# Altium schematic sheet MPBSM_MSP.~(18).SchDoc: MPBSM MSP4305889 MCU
size 431 x 279 mm; Date: Not shown in title block; ApprovedBy: Not shown in title block; CheckedBy: Not shown in title block; Author: Not shown in title block; CompanyName: Not shown in title block; Engineer: Not shown in title block; Organization: Not shown in title block; Address1: Not shown in title block; Address2: Not shown in title block; Address3: Not shown in title block; Address4: Not shown in title block; DocumentNumber: 6; Revision: Use project parameter SCH_Rev; SheetNumber: 6; SheetTotal: 12; PageSetup: Record=PageOptions¦CenterHorizontal=True¦CenterVertical=True¦PrintScale=0.62¦XCorrection=1.00¦YCorrection=1.00¦PrintKind=0¦BorderSize=5000000¦LeftOffset=0¦BottomOffset=0¦Orientation=2¦PaperLength=1000¦PaperWidth=1000¦Scale=100¦PaperSource=15¦PrintQuality=600¦MediaType=1¦DitherType=10¦PaperKind=Letter¦PrintScaleMode=1
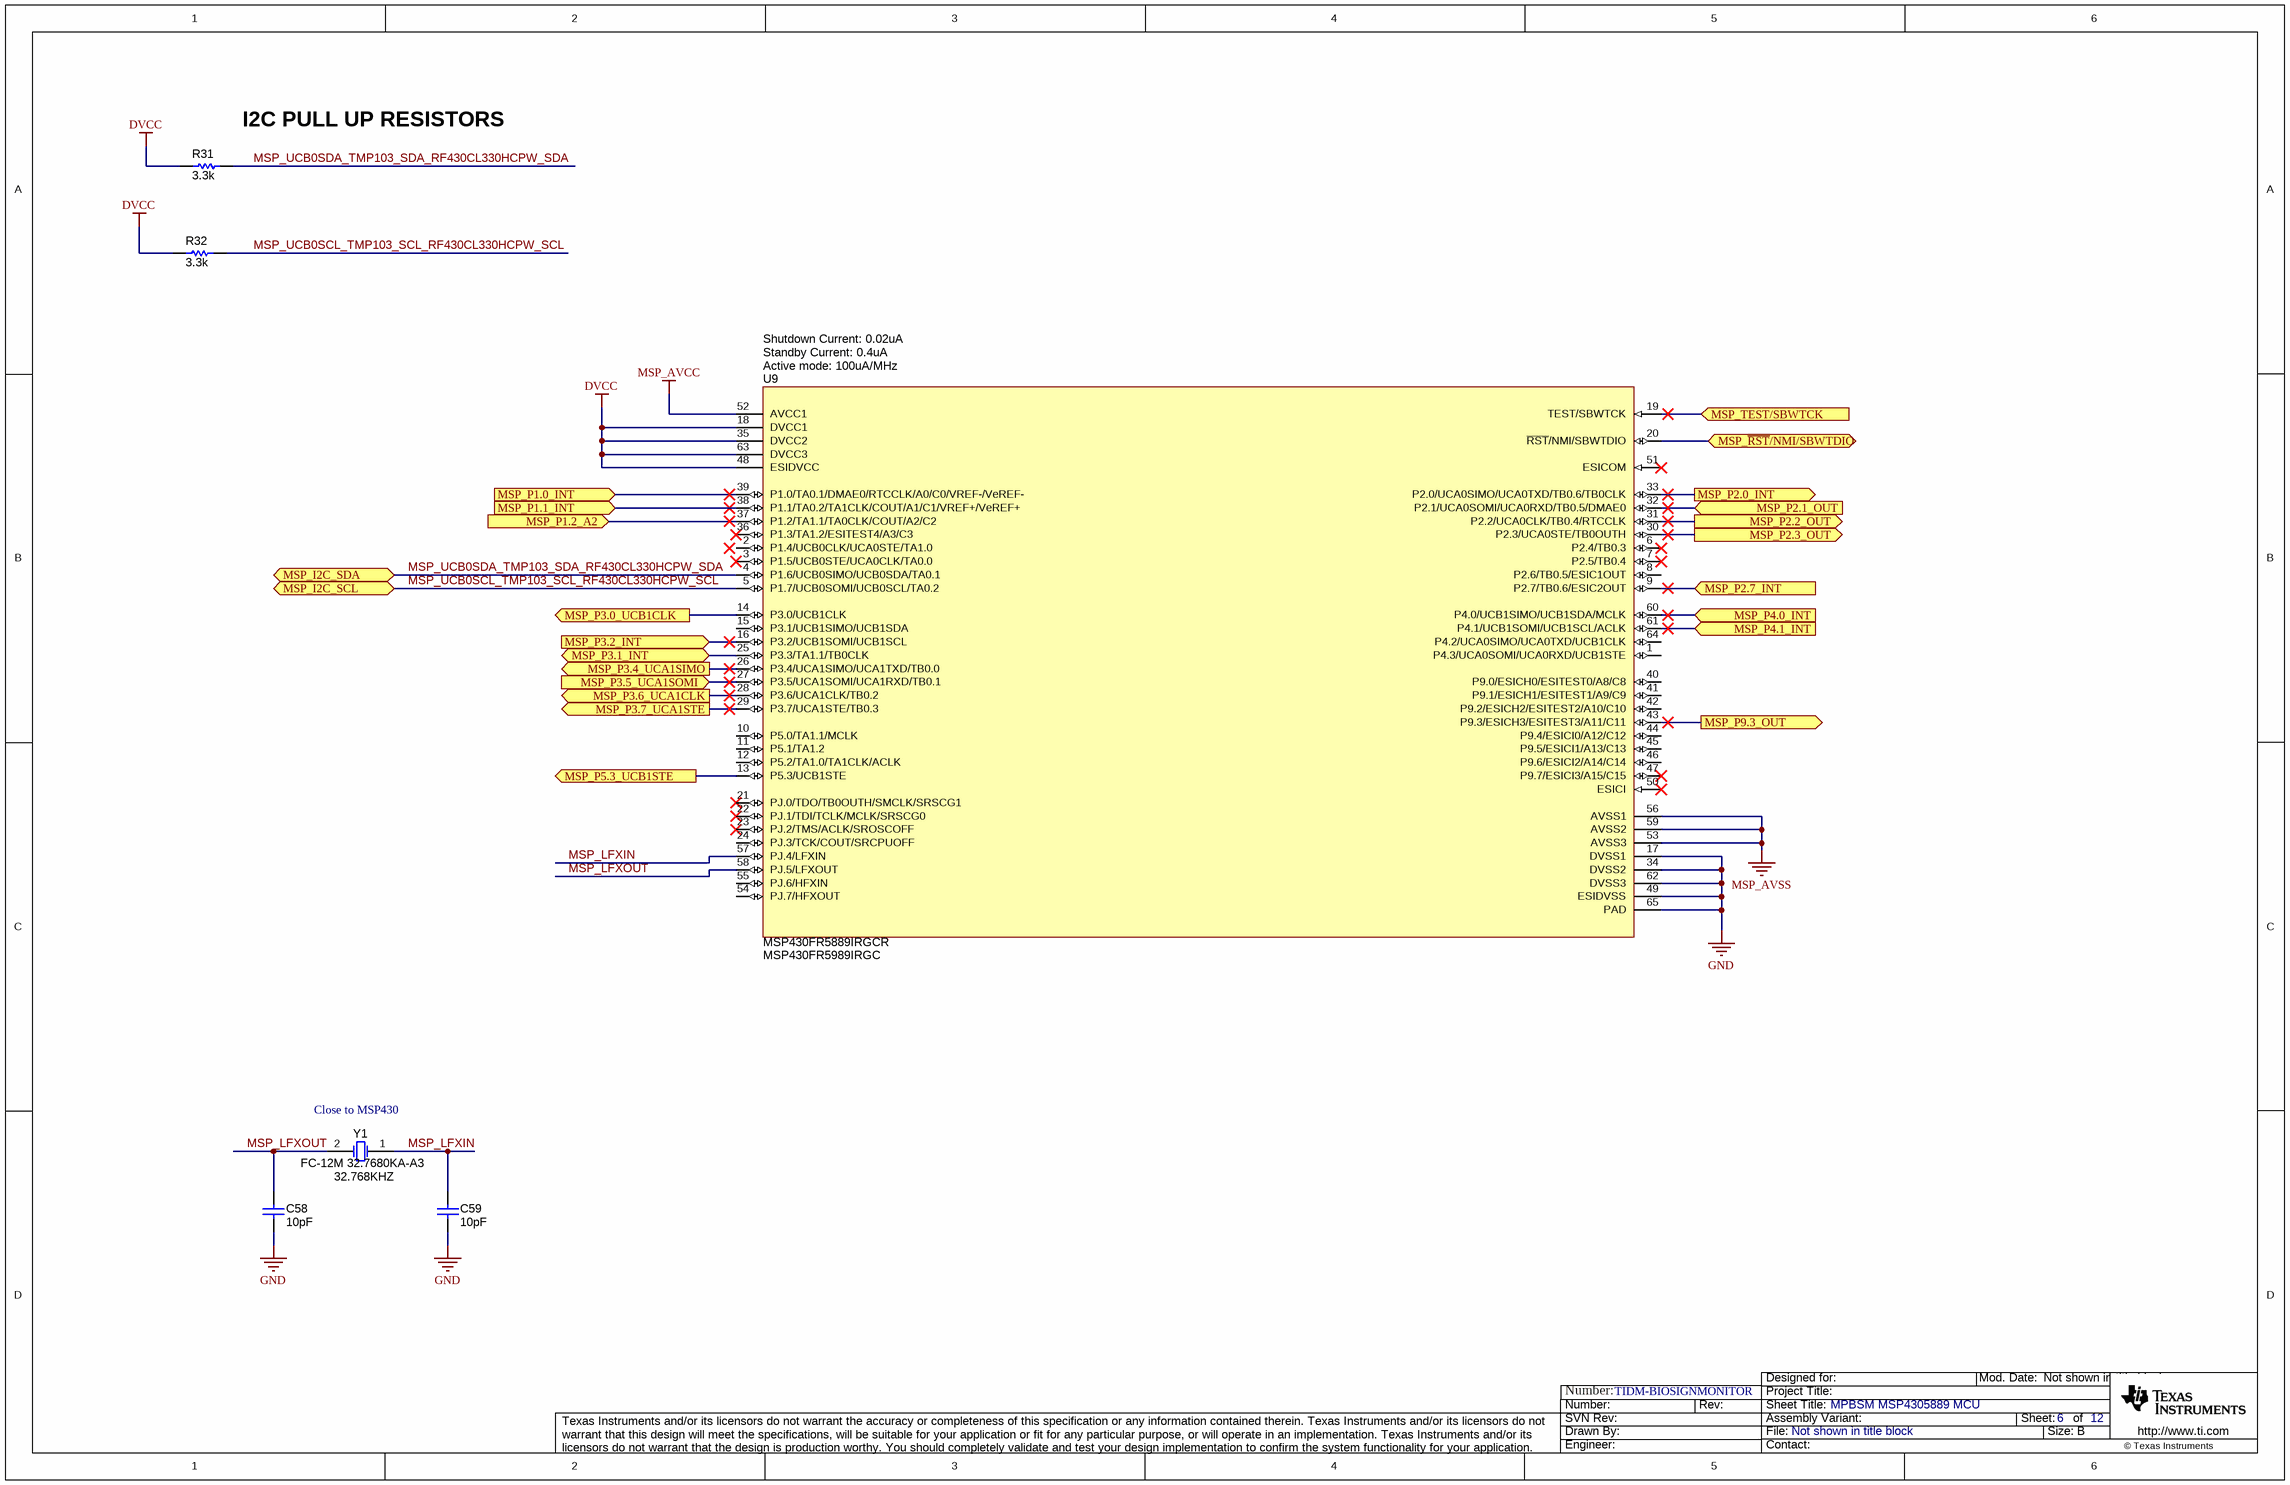
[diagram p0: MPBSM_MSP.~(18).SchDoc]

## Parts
C58  ValueDisplayed: 10pF  [0603]  (hidden comment: 06035A100JAT2A)
C59  ValueDisplayed: 10pF  [0603]  (hidden comment: 06035A100JAT2A)
R31  ValueDisplayed: 3.3k  [0402]  (hidden comment: CRCW04023K30JNED)
R32  ValueDisplayed: 3.3k  [0402]  (hidden comment: CRCW04023K30JNED)
U9  MSP430FR5889IRGCR  Alternate PartNumber: MSP430FR5989IRGC  Active mode: 100uA/MHz  Standby Current: 0.4uA  Shutdown Current: 0.02uA  [RGC0064B]
Y1  FC-12M 32.7680KA-A3  Frequency: 32.768KHZ  [Epson_FC-12M]

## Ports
MSP_I2C_SCL (bidir), MSP_I2C_SDA (bidir), MSP_P1.0_INT (in), MSP_P1.1_INT (in), MSP_P1.2_A2 (in), MSP_P2.0_INT (out), MSP_P2.1_OUT (in), MSP_P2.2_OUT (out), MSP_P2.3_OUT (out), MSP_P2.7_INT (in), MSP_P3.0_UCB1CLK (out), MSP_P3.1_INT (bidir), MSP_P3.2_INT (in), MSP_P3.4_UCA1SIMO (out), MSP_P3.5_UCA1SOMI (in), MSP_P3.6_UCA1CLK (out), MSP_P3.7_UCA1STE (out), MSP_P4.0_INT (in), MSP_P4.1_INT (in), MSP_P5.3_UCB1STE (out), MSP_P9.3_OUT (out), MSP_TEST/SBWTCK (in), MSP_~{RST}/NMI/SBWTDIO (bidir)

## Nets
DVCC: R31.1 R32.1 U9.18(DVCC1) U9.35(DVCC2) U9.48(ESIDVCC) U9.63(DVCC3)
GND: C58.2 C59.2 U9.17(DVSS1) U9.34(DVSS2) U9.49(ESIDVSS) U9.62(DVSS3) U9.65(PAD)
MSP_AVCC: U9.52(AVCC1)
MSP_AVSS: U9.53(AVSS3) U9.56(AVSS1) U9.59(AVSS2)
MSP_LFXIN: C59.1 U9.57(PJ.4/LFXIN) Y1.1(OSC1)
MSP_LFXOUT: C58.1 U9.58(PJ.5/LFXOUT) Y1.2(OSC2)
MSP_P1.0_INT: U9.39(P1.0/TA0.1/DMAE0/RTCCLK/A0/C0/VREF-/VeREF-) ; port MSP_P1.0_INT
MSP_P1.1_INT: U9.38(P1.1/TA0.2/TA1CLK/COUT/A1/C1/VREF+/VeREF+) ; port MSP_P1.1_INT
MSP_P1.2_A2: U9.37(P1.2/TA1.1/TA0CLK/COUT/A2/C2) ; port MSP_P1.2_A2
MSP_P2.0_INT: U9.33(P2.0/UCA0SIMO/UCA0TXD/TB0.6/TB0CLK) ; port MSP_P2.0_INT
MSP_P2.1_OUT: U9.32(P2.1/UCA0SOMI/UCA0RXD/TB0.5/DMAE0) ; port MSP_P2.1_OUT
MSP_P2.2_OUT: U9.31(P2.2/UCA0CLK/TB0.4/RTCCLK) ; port MSP_P2.2_OUT
MSP_P2.3_OUT: U9.30(P2.3/UCA0STE/TB0OUTH) ; port MSP_P2.3_OUT
MSP_P2.7_INT: U9.9(P2.7/TB0.6/ESIC2OUT) ; port MSP_P2.7_INT
MSP_P3.0_UCB1CLK: U9.14(P3.0/UCB1CLK) ; port MSP_P3.0_UCB1CLK
MSP_P3.1_INT: U9.25(P3.3/TA1.1/TB0CLK) ; port MSP_P3.1_INT
MSP_P3.2_INT: U9.16(P3.2/UCB1SOMI/UCB1SCL) ; port MSP_P3.2_INT
MSP_P3.4_UCA1SIMO: U9.26(P3.4/UCA1SIMO/UCA1TXD/TB0.0) ; port MSP_P3.4_UCA1SIMO
MSP_P3.5_UCA1SOMI: U9.27(P3.5/UCA1SOMI/UCA1RXD/TB0.1) ; port MSP_P3.5_UCA1SOMI
MSP_P3.6_UCA1CLK: U9.28(P3.6/UCA1CLK/TB0.2) ; port MSP_P3.6_UCA1CLK
MSP_P3.7_UCA1STE: U9.29(P3.7/UCA1STE/TB0.3) ; port MSP_P3.7_UCA1STE
MSP_P4.0_INT: U9.60(P4.0/UCB1SIMO/UCB1SDA/MCLK) ; port MSP_P4.0_INT
MSP_P4.1_INT: U9.61(P4.1/UCB1SOMI/UCB1SCL/ACLK) ; port MSP_P4.1_INT
MSP_P5.3_UCB1STE: U9.13(P5.3/UCB1STE) ; port MSP_P5.3_UCB1STE
MSP_P9.3_OUT: U9.43(P9.3/ESICH3/ESITEST3/A11/C11) ; port MSP_P9.3_OUT
MSP_~{RST}/NMI/SBWTDIO: U9.20(~{RST}/NMI/SBWTDIO) ; port MSP_~{RST}/NMI/SBWTDIO
MSP_TEST/SBWTCK: U9.19(TEST/SBWTCK) ; port MSP_TEST/SBWTCK
MSP_UCB0SCL_TMP103_SCL_RF430CL330HCPW_SCL: R32.2 U9.5(P1.7/UCB0SOMI/UCB0SCL/TA0.2) ; port MSP_I2C_SCL
MSP_UCB0SDA_TMP103_SDA_RF430CL330HCPW_SDA: R31.2 U9.4(P1.6/UCB0SIMO/UCB0SDA/TA0.1) ; port MSP_I2C_SDA

Not connected (* = marked no-connect by the designer): U9 1(P4.3/UCA0SOMI/UCA0RXD/UCB1STE) 2(P1.4/UCB0CLK/UCA0STE/TA1.0) 3(P1.5/UCB0STE/UCA0CLK/TA0.0)* 6(P2.4/TB0.3)* 7(P2.5/TB0.4)* 8(P2.6/TB0.5/ESIC1OUT) 10(P5.0/TA1.1/MCLK) 11(P5.1/TA1.2) 12(P5.2/TA1.0/TA1CLK/ACLK) 15(P3.1/UCB1SIMO/UCB1SDA) 21(PJ.0/TDO/TB0OUTH/SMCLK/SRSCG1)* 22(PJ.1/TDI/TCLK/MCLK/SRSCG0)* 23(PJ.2/TMS/ACLK/SROSCOFF)* 24(PJ.3/TCK/COUT/SRCPUOFF) 36(P1.3/TA1.2/ESITEST4/A3/C3)* 40(P9.0/ESICH0/ESITEST0/A8/C8) 41(P9.1/ESICH1/ESITEST1/A9/C9) 42(P9.2/ESICH2/ESITEST2/A10/C10) 44(P9.4/ESICI0/A12/C12) 45(P9.5/ESICI1/A13/C13) 46(P9.6/ESICI2/A14/C14) 47(P9.7/ESICI3/A15/C15)* 50(ESICI)* 51(ESICOM)* 54(PJ.7/HFXOUT) 55(PJ.6/HFXIN) 64(P4.2/UCA0SIMO/UCA0TXD/UCB1CLK)

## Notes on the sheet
- (near R31) I2C PULL UP RESISTORS
- (near Y1) Close to MSP430
- Number:
- TIDM-BIOSIGNMONITOR

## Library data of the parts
C58 C59 = 06035A100JAT2A: CAP, CERM, 10 pF, 50 V, +/- 5%, C0G/NP0, 0603; Manufacturer: AVX; Polarized: N; CompType: Capacitor; Value: 10pF; U/M: EA; Cap_F: 0.00000000001; Tolerance_%: 5; ESR_ohm: 0.403; Value1: 0.403 ohm; VDC_V: 50; Value2: 50V; TaMin_C: -55; TaMax_C: 125
R31 R32 = CRCW04023K30JNED: RES, 3.3 k, 5%, 0.063 W, 0402; Manufacturer: Vishay-Dale; CompType: Resistor; Value: 3.3k; Res_ohm: 3300; Value_Code: 3k30; Tolerance_%: 5; Power_W: 0.063; Value2: 0.063W; VDC_V: 50; TempCo: 200 ppm/C; EIA_Code: E24; U/M: EA
U9 = MSP430FR5889IRGCR: Mixed-Signal Microcontrollers, RGC0064B; Alternate Manufacturer: Texas Instruments; SymbolCreator: Altium; CompType: IC; U/M: EA; SupplyVoltage: 1.8 V to 3.6 V; SupplyVoltageMax_V: 3.6 V; SupplyVoltageMin_V: 1.8 V; TaMax_C: -40 °C; TaMin_C: +125 °C
Y1 = FC-12M 32.7680KA-A3: Crystal, 32.768kHz, 12.5pF, SMD; Manufacturer: Epson; SymbolCreator: a0412235; U/M: EA; TaMin_C: -40 °C; TaMax_C: 85 °C; Value2: 90 kOhm; Value3: ±20ppm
